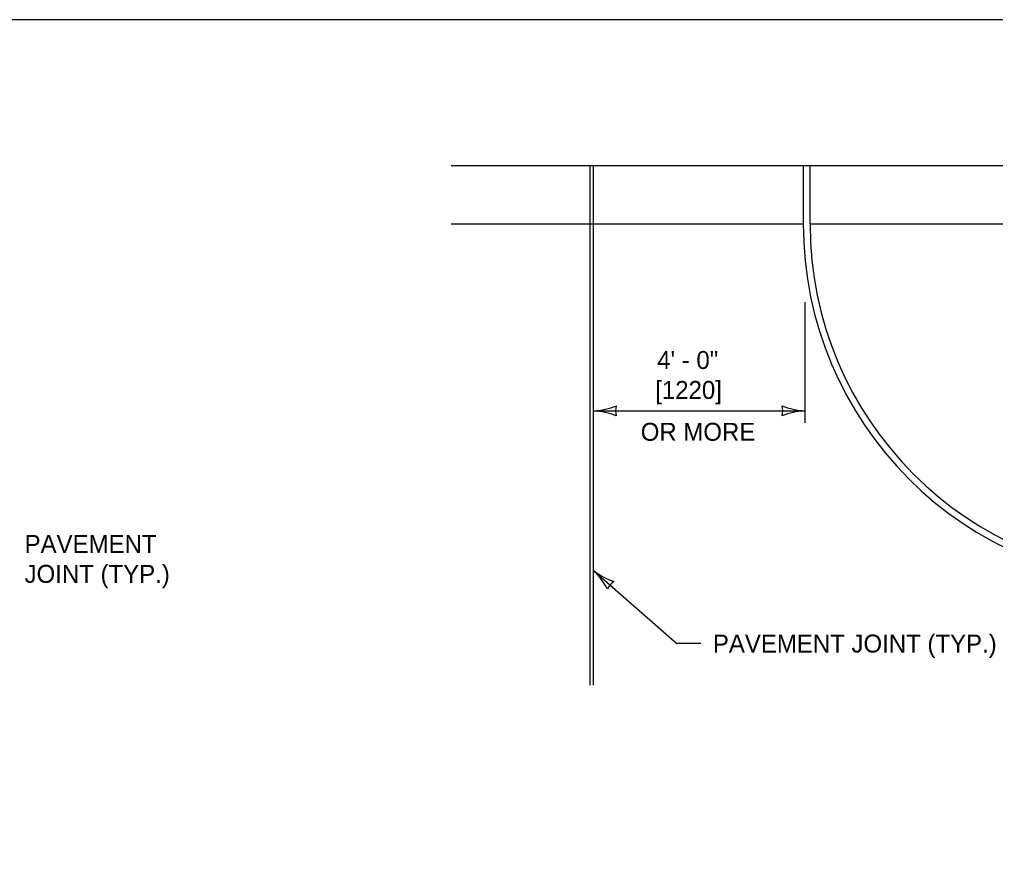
# Model space of a CAD drawing. Extents: x 49991.4 to 50021, y 49987.6 to 50011.4.
# Drawn here: x 50009.515 to 50012.78, y 49996.188 to 49998.999 of the extents above; entities that cross this region are included whole.
import ezdxf

# ---------------------------------------------------------------- set-up
doc = ezdxf.new("R2010")
doc.units = 0
for name, color, linetype in [('Level 1', 7, 'Continuous'), ('Level 2', 7, 'Continuous'), ('Level 3', 7, 'Continuous'), ('Level 62', 7, 'Continuous')]:
    doc.layers.add(name, color=color, linetype=linetype)

msp = doc.modelspace()

# ---------------------------------------------------------------- linework, layer by layer
at = {"layer": 'Level 1'}
for p, q in [((50015.0211, 49998.5105), (50010.9589, 49998.5105)), ((50011.4234, 49996.7746), (50011.4234, 49998.5105)), ((50011.4353, 49996.7746), (50011.4353, 49998.5105)), ((50012.1367, 49998.3155), (50010.9589, 49998.3155)), ((50014.5233, 49998.3155), (50012.1592, 49998.3155))]:
    msp.add_line(p, q, dxfattribs=at)
msp.add_lwpolyline([(49999.3835, 49998.9992), (50016.7501, 49998.9992), (50016.7501, 49987.7988), (49999.3835, 49987.7988)], close=True, dxfattribs=at)
msp.add_lwpolyline([(50012.1592, 49998.3155), (50012.1592, 49998.5105), (50012.1367, 49998.5105), (50012.1367, 49998.3155)], dxfattribs=at)
for radius in [1.2045, 1.182]:
    msp.add_arc((50013.3412, 49998.3155), radius, 180, 0, dxfattribs=at)
at = {"layer": 'Level 3'}
for p, q in [((50012.1419, 49998.0548), (50012.1419, 49997.651)), ((50011.4353, 49997.691), (50012.1419, 49997.691)), ((50011.4353, 49997.1578), (50011.7143, 49996.9132)), ((50011.7943, 49996.9132), (50011.7143, 49996.9132))]:
    msp.add_line(p, q, dxfattribs=at)
for centre, radius, start, end in [((50011.4238, 49997.9237), 0.233, 272.8273, 292.0772), ((50011.4261, 49997.4689), 0.2223, 67.456, 87.6395), ((50011.5635, 49997.691), 0.0548, 162.1388, 197.8612), ((50012.151, 49997.9132), 0.2223, 247.456, 267.6395), ((50012.0136, 49997.691), 0.0548, 342.1388, 17.8612), ((50012.1533, 49997.4583), 0.233, 92.8273, 112.0772), ((50011.282, 49996.9968), 0.2223, 26.2193, 46.4028), ((50011.58, 49997.3404), 0.233, 231.5906, 250.8404), ((50011.5317, 49997.0733), 0.0548, 120.9021, 156.6244)]:
    msp.add_arc(centre, radius, start, end, dxfattribs=at)
at = {"layer": 'Level 62'}
msp.add_line((50011.4353, 49996.7746), (50011.4353, 49998.5105), dxfattribs=at)

# ---------------------------------------------------------------- texts
at = {"layer": 'Level 2'}
for s, p in [('4\' - 0"', (50011.648, 49997.831)), ('[1220]', (50011.6414, 49997.731)), ('OR MORE', (50011.5929, 49997.591)), ('PAVEMENT', (50009.532, 49997.2161)), ('JOINT (TYP.)', (50009.532, 49997.1161)), ('PAVEMENT JOINT (TYP.)', (50011.8343, 49996.8832))]:
    msp.add_text(s, height=0.06, dxfattribs=at).set_placement(p)

doc.saveas('drawing.dxf')
